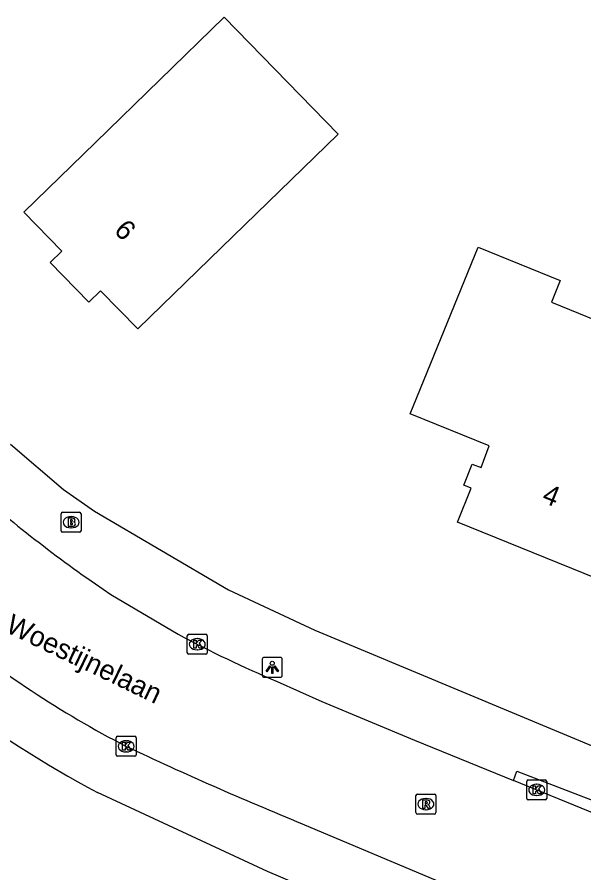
# Model space of a CAD drawing. Extents: x 161141 to 161601, y 381708 to 382245.
# Drawn here: x 161283.09 to 161311.44, y 381875.71 to 381918.52 of the extents above; entities that cross this region are included whole.
import ezdxf

# ---------------------------------------------------------------- set-up
doc = ezdxf.new("R2010")
doc.units = 0
for name, color, linetype in [('IMGEO_Brandkraan', 7, 'Continuous'), ('IMGEO_Kolk', 7, 'Continuous'), ('IMGEO_Lichtpunt', 7, 'Continuous'), ('IMGEO_Openbare_ruimte_label', 7, 'Continuous'), ('IMGEO_Pand', 7, 'Continuous'), ('IMGEO_Pand_nummerreeks', 7, 'Continuous'), ('IMGEO_Rijbaan_lokaal_open', 7, 'Continuous'), ('IMGEO_Rioolput', 7, 'Continuous'), ('IMGEO_Voetpad_open', 7, 'Continuous')]:
    doc.layers.add(name, color=color, linetype=linetype)

msp = doc.modelspace()

# ---------------------------------------------------------------- linework, layer by layer
at = {"layer": 'IMGEO_Brandkraan'}
for p, q in [((161285.289, 381892.824), (161285.289, 381893.676)), ((161285.364, 381893.75), (161286.216, 381893.75)), ((161286.29, 381893.676), (161286.29, 381892.824)), ((161285.777, 381893.53), (161285.802, 381893.53)), ((161286.216, 381892.75), (161285.364, 381892.75)), ((161285.8, 381892.97), (161285.775, 381892.97))]:
    msp.add_line(p, q, dxfattribs=at)
for points in [[(161285.289, 381892.824), (161285.289, 381893.676)], [(161285.364, 381893.75), (161286.216, 381893.75)], [(161286.29, 381893.676), (161286.29, 381892.824)], [(161285.637, 381893.45), (161285.637, 381893.05), (161285.85, 381893.05)], [(161285.868, 381893.45), (161285.637, 381893.45)], [(161285.816, 381893.369), (161285.762, 381893.369), (161285.762, 381893.293)], [(161285.762, 381893.293), (161285.815, 381893.293)], [(161285.824, 381893.217), (161285.762, 381893.217), (161285.762, 381893.136)], [(161286.216, 381892.75), (161285.364, 381892.75)], [(161285.762, 381893.136), (161285.824, 381893.136)]]:
    msp.add_lwpolyline(points, dxfattribs=at)
for centre, radius, start, end in [((161285.366, 381893.674), 0.0765, 91.552, 178.448), ((161285.366, 381893.674), 0.0765, 91.552, 178.448), ((161286.214, 381893.674), 0.0765, 1.552, 88.448), ((161286.214, 381893.674), 0.0765, 1.552, 88.448), ((161285.817, 381893.331), 0.0379, 267.8285, 90.9355), ((161285.825, 381893.176), 0.0404, 269.8759, 90.5077), ((161285.872, 381893.305), 0.145, 59.4692, 91.5367), ((161285.897, 381893.352), 0.0922, 285.5137, 58.1501), ((161285.902, 381893.16), 0.105, 301.3115, 78.989), ((161285.366, 381892.826), 0.0765, 181.552, 268.448), ((161285.366, 381892.826), 0.0765, 181.552, 268.448), ((161285.856, 381893.301), 0.251, 268.6676, 293.5347), ((161286.214, 381892.826), 0.0765, 271.552, 358.448), ((161286.214, 381892.826), 0.0765, 271.552, 358.448)]:
    msp.add_arc(centre, radius, start, end, dxfattribs=at)
for centre, major_axis, ratio, start_param, end_param in [((161285.776, 381893.25), (-0.387, 0.002), 0.722429, 4.712389, 7.853982), ((161285.801, 381893.25), (-0.39, 0.002), 0.717154, 1.570796, 4.712389)]:
    msp.add_ellipse(centre, major_axis=major_axis, ratio=ratio, start_param=start_param, end_param=end_param, dxfattribs=at)
at = {"layer": 'IMGEO_Kolk'}
for p, q in [((161291.676, 381887.648), (161292.528, 381887.648)), ((161291.601, 381886.722), (161291.601, 381887.574)), ((161292.089, 381887.428), (161292.114, 381887.428)), ((161292.602, 381887.574), (161292.602, 381886.722)), ((161292.112, 381886.868), (161292.087, 381886.868)), ((161292.528, 381886.648), (161291.676, 381886.648)), ((161288.043, 381881.614), (161288.043, 381882.466)), ((161288.118, 381882.54), (161288.97, 381882.54)), ((161289.044, 381882.466), (161289.044, 381881.614)), ((161288.531, 381882.32), (161288.556, 381882.32)), ((161288.554, 381881.76), (161288.529, 381881.76)), ((161288.97, 381881.54), (161288.118, 381881.54)), ((161308.652, 381880.359), (161309.504, 381880.359)), ((161308.577, 381879.433), (161308.577, 381880.285)), ((161309.065, 381880.139), (161309.09, 381880.139)), ((161309.578, 381880.285), (161309.578, 381879.433)), ((161309.088, 381879.579), (161309.063, 381879.579)), ((161309.504, 381879.359), (161308.652, 381879.359))]:
    msp.add_line(p, q, dxfattribs=at)
for points in [[(161291.676, 381887.648), (161292.528, 381887.648)], [(161291.601, 381886.722), (161291.601, 381887.574)], [(161291.922, 381887.348), (161292.045, 381887.348), (161292.045, 381887.197), (161292.175, 381887.348), (161292.339, 381887.348), (161292.193, 381887.197), (161292.346, 381886.948), (161292.194, 381886.948), (161292.109, 381887.112), (161292.045, 381887.045), (161292.045, 381886.948), (161291.922, 381886.948), (161291.922, 381887.348)], [(161292.602, 381887.574), (161292.602, 381886.722)], [(161292.528, 381886.648), (161291.676, 381886.648)], [(161288.043, 381881.614), (161288.043, 381882.466)], [(161288.118, 381882.54), (161288.97, 381882.54)], [(161289.044, 381882.466), (161289.044, 381881.614)], [(161288.364, 381882.24), (161288.487, 381882.24), (161288.487, 381882.089), (161288.617, 381882.24), (161288.781, 381882.24), (161288.635, 381882.089), (161288.788, 381881.84), (161288.636, 381881.84), (161288.551, 381882.004), (161288.487, 381881.937), (161288.487, 381881.84), (161288.364, 381881.84), (161288.364, 381882.24)], [(161288.97, 381881.54), (161288.118, 381881.54)], [(161308.652, 381880.359), (161309.504, 381880.359)], [(161308.577, 381879.433), (161308.577, 381880.285)], [(161308.898, 381880.059), (161309.021, 381880.059), (161309.021, 381879.908), (161309.151, 381880.059), (161309.315, 381880.059), (161309.169, 381879.908), (161309.322, 381879.659), (161309.17, 381879.659), (161309.085, 381879.823), (161309.021, 381879.756), (161309.021, 381879.659), (161308.898, 381879.659), (161308.898, 381880.059)], [(161309.578, 381880.285), (161309.578, 381879.433)], [(161309.504, 381879.359), (161308.652, 381879.359)]]:
    msp.add_lwpolyline(points, dxfattribs=at)
for centre, start, end in [((161291.678, 381887.572), 91.552, 178.448), ((161291.678, 381887.572), 91.552, 178.448), ((161292.526, 381887.572), 1.552, 88.448), ((161292.526, 381887.572), 1.552, 88.448), ((161291.678, 381886.724), 181.552, 268.448), ((161291.678, 381886.724), 181.552, 268.448), ((161292.526, 381886.724), 271.552, 358.448), ((161292.526, 381886.724), 271.552, 358.448), ((161288.12, 381882.464), 91.552, 178.448), ((161288.12, 381882.464), 91.552, 178.448), ((161288.968, 381882.464), 1.552, 88.448), ((161288.968, 381882.464), 1.552, 88.448), ((161288.12, 381881.616), 181.552, 268.448), ((161288.12, 381881.616), 181.552, 268.448), ((161288.968, 381881.616), 271.552, 358.448), ((161288.968, 381881.616), 271.552, 358.448), ((161308.654, 381880.283), 91.552, 178.448), ((161308.654, 381880.283), 91.552, 178.448), ((161309.502, 381880.283), 1.552, 88.448), ((161309.502, 381880.283), 1.552, 88.448), ((161308.654, 381879.435), 181.552, 268.448), ((161308.654, 381879.435), 181.552, 268.448), ((161309.502, 381879.435), 271.552, 358.448), ((161309.502, 381879.435), 271.552, 358.448)]:
    msp.add_arc(centre, 0.0765, start, end, dxfattribs=at)
for centre, major_axis, ratio, start_param, end_param in [((161292.088, 381887.148), (-0.387, 0.002), 0.722429, 4.712389, 7.853982), ((161292.113, 381887.148), (-0.39, 0.002), 0.717154, 1.570796, 4.712389), ((161288.53, 381882.04), (-0.387, 0.002), 0.722429, 4.712389, 7.853982), ((161288.555, 381882.04), (-0.39, 0.002), 0.717154, 1.570796, 4.712389), ((161309.064, 381879.859), (-0.387, 0.002), 0.722429, 4.712389, 7.853982), ((161309.089, 381879.859), (-0.39, 0.002), 0.717154, 1.570796, 4.712389)]:
    msp.add_ellipse(centre, major_axis=major_axis, ratio=ratio, start_param=start_param, end_param=end_param, dxfattribs=at)
at = {"layer": 'IMGEO_Lichtpunt'}
for p, q in [((161295.351, 381886.397), (161295.351, 381885.59)), ((161295.351, 381886.397), (161295.351, 381885.59)), ((161296.253, 381886.492), (161295.445, 381886.492)), ((161296.253, 381886.492), (161295.445, 381886.492)), ((161296.347, 381885.59), (161296.347, 381886.397)), ((161296.347, 381885.59), (161296.347, 381886.397)), ((161295.445, 381885.496), (161296.253, 381885.496)), ((161295.445, 381885.496), (161296.253, 381885.496))]:
    msp.add_line(p, q, dxfattribs=at)
for points in [[(161295.725, 381886.061), (161295.764, 381886.033), (161295.576, 381885.771), (161295.538, 381885.798), (161295.725, 381886.061)], [(161295.827, 381886.013), (161295.874, 381886.013), (161295.874, 381885.691), (161295.827, 381885.691), (161295.827, 381886.013)], [(161295.937, 381886.033), (161295.975, 381886.06), (161296.162, 381885.798), (161296.123, 381885.77), (161295.937, 381886.033)]]:
    msp.add_lwpolyline(points, dxfattribs=at)
msp.add_circle((161295.85, 381886.195), 0.0994, dxfattribs=at)
for centre, start, end in [((161295.445, 381886.397), 90, 180), ((161295.445, 381886.397), 90, 180), ((161296.253, 381886.397), 0, 90), ((161296.253, 381886.397), 0, 90), ((161295.445, 381885.59), 180, 270), ((161295.445, 381885.59), 180, 270), ((161296.253, 381885.59), 270, 0), ((161296.253, 381885.59), 270, 360)]:
    msp.add_arc(centre, 0.0946, start, end, dxfattribs=at)
at = {"layer": 'IMGEO_Pand'}
for points in [[(161289.127, 381902.92), (161287.265, 381904.835), (161286.675, 381904.261), (161284.744, 381906.246), (161285.326, 381906.813), (161283.423, 381908.769), (161287.007, 381912.256), (161293.446, 381918.522), (161299.144, 381912.667), (161292.711, 381906.407), (161289.127, 381902.92)], [(161316.193, 381910.265), (161323.278, 381907.381), (161321.194, 381902.259), (161317.489, 381903.766), (161313.947, 381895.06), (161312.062, 381890.428), (161305.111, 381893.257), (161305.8, 381894.95), (161305.424, 381895.103), (161305.852, 381896.154), (161306.302, 381895.986), (161306.706, 381897.067), (161302.753, 381898.676), (161306.145, 381907.012), (161310.258, 381905.339), (161309.82, 381904.264), (161313.34, 381902.832), (161314.245, 381905.055), (161314.097, 381905.115), (161316.193, 381910.265)]]:
    msp.add_lwpolyline(points, dxfattribs=at)
at = {"layer": 'IMGEO_Rijbaan_lokaal_open'}
for points in [[(161287.011, 381890.162), (161287.39, 381889.901), (161287.77, 381889.643), (161291.143, 381887.655)], [(161296.095, 381885.289), (161298.323, 381884.279), (161302.959, 381882.345), (161307.913, 381880.338)], [(161318.426, 381876.273), (161316.431, 381876.868), (161312.405, 381878.498), (161307.913, 381880.338)], [(161297.345, 381878.162), (161313.303, 381871.448)]]:
    msp.add_lwpolyline(points, dxfattribs=at)
for centre, radius, start, end in [((161326.411, 381946.909), 69.084, 228.08278, 235.22747), ((161311.453, 381926.489), 50.005, 230.1076, 242.7376), ((161316.865, 381935.126), 53.992, 241.5489, 247.3754), ((161368.588, 382051.732), 187.622, 244.748, 247.68406)]:
    msp.add_arc(centre, radius, start, end, dxfattribs=at)
at = {"layer": 'IMGEO_Rioolput'}
for p, q in [((161303.035, 381878.722), (161303.035, 381879.574)), ((161303.11, 381879.648), (161303.962, 381879.648)), ((161304.036, 381879.574), (161304.036, 381878.722)), ((161303.523, 381879.428), (161303.548, 381879.428)), ((161303.962, 381878.648), (161303.11, 381878.648)), ((161303.546, 381878.868), (161303.521, 381878.868))]:
    msp.add_line(p, q, dxfattribs=at)
for points in [[(161303.035, 381878.722), (161303.035, 381879.574)], [(161303.11, 381879.648), (161303.962, 381879.648)], [(161304.036, 381879.574), (161304.036, 381878.722)], [(161303.624, 381879.346), (161303.372, 381879.348), (161303.372, 381878.948)], [(161303.372, 381878.948), (161303.496, 381878.948), (161303.496, 381879.11), (161303.507, 381879.11)], [(161303.55, 381879.267), (161303.496, 381879.267), (161303.496, 381879.186)], [(161303.496, 381879.186), (161303.548, 381879.186)], [(161303.554, 381879.081), (161303.625, 381878.948), (161303.765, 381878.948), (161303.7, 381879.074)], [(161303.962, 381878.648), (161303.11, 381878.648)]]:
    msp.add_lwpolyline(points, dxfattribs=at)
for centre, radius, start, end in [((161303.112, 381879.572), 0.0765, 91.552, 178.448), ((161303.112, 381879.572), 0.0765, 91.552, 178.448), ((161303.96, 381879.572), 0.0765, 1.552, 88.448), ((161303.96, 381879.572), 0.0765, 1.552, 88.448), ((161303.506, 381879.057), 0.0533, 26.0293, 88.6989), ((161303.532, 381879.375), 0.19, 274.7715, 282.9687), ((161303.556, 381879.171), 0.0964, 77.0061, 93.1865), ((161303.57, 381879.228), 0.0378, 276.6634, 79.6772), ((161303.623, 381879.236), 0.109, 350.3612, 89.416), ((161303.621, 381879.236), 0.112, 277.5842, 350.9817), ((161303.605, 381879.021), 0.108, 29.5134, 73.7905), ((161303.112, 381878.724), 0.0765, 181.552, 268.448), ((161303.112, 381878.724), 0.0765, 181.552, 268.448), ((161303.96, 381878.724), 0.0765, 271.552, 358.448), ((161303.96, 381878.724), 0.0765, 271.552, 358.448)]:
    msp.add_arc(centre, radius, start, end, dxfattribs=at)
for centre, major_axis, ratio, start_param, end_param in [((161303.522, 381879.148), (-0.387, 0.002), 0.722429, 4.712389, 7.853982), ((161303.547, 381879.148), (-0.39, 0.002), 0.717154, 1.570796, 4.712389)]:
    msp.add_ellipse(centre, major_axis=major_axis, ratio=ratio, start_param=start_param, end_param=end_param, dxfattribs=at)
at = {"layer": 'IMGEO_Voetpad_open'}
for points in [[(161282.757, 381897.162), (161285.416, 381894.897), (161286.952, 381893.797), (161293.664, 381889.876), (161297.982, 381887.859), (161317.522, 381879.697)], [(161307.913, 381880.338), (161308.089, 381880.805), (161318.602, 381876.74), (161318.426, 381876.273)], [(161307.156, 381870.851), (161306.308, 381871.219), (161295.616, 381875.775), (161287.109, 381879.723)]]:
    msp.add_lwpolyline(points, dxfattribs=at)
msp.add_arc((161316.981, 381935.088), 62.91, 225.19754, 241.65079, dxfattribs=at)

# ---------------------------------------------------------------- texts
at = {"layer": 'IMGEO_Openbare_ruimte_label'}
msp.add_text('Karel van den Woestijnelaan', height=1, rotation=334.2805, dxfattribs=at).set_placement((161274.682, 381891.533))
at = {"layer": 'IMGEO_Pand_nummerreeks'}
for s, rotation, p in [('6', 314.2809, (161287.887, 381907.8)), ('4', 337.8541, (161309.282, 381894.281))]:
    msp.add_text(s, height=1, rotation=rotation, dxfattribs=at).set_placement(p)

doc.saveas('drawing.dxf')
